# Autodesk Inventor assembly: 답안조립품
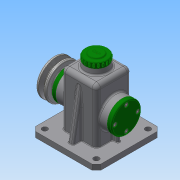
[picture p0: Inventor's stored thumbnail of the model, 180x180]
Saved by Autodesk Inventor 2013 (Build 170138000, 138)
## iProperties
Created: 2018-10
Part Number: 답안조립품
Document SubType Name: Assembly
Designer: Administrator
Author: Administrator
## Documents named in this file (14)
- C:\Users\Administrator\Desktop\481013V1014\답안조립품.iam
- C:\Users\Administrator\Desktop\481013V1014\본체.ipt
- C:\Users\Administrator\Desktop\481013V1014\V-벨트풀리.ipt
- C:\Users\Administrator\Desktop\481013V1014\뒤커버.ipt
- C:\Users\Administrator\Desktop\481013V1014\멈춤링 15 x 1.ipt
- C:\Users\Administrator\Desktop\481013V1014\베어링 15 x 35 x 11.ipt
- C:\Users\Administrator\Desktop\481013V1014\볼트 M4 x 10.ipt
- C:\Users\Administrator\Desktop\481013V1014\볼트 M6 x 12.ipt
- C:\Users\Administrator\Desktop\481013V1014\상부캡.ipt
- C:\Users\Administrator\Desktop\481013V1014\앞커버.ipt
- C:\Users\Administrator\Desktop\481013V1014\오일실 15 25 7.ipt
- C:\Users\Administrator\Desktop\481013V1014\와셔.ipt
- C:\Users\Administrator\Desktop\481013V1014\축.ipt
- C:\Users\Administrator\Desktop\481013V1014\키 5 x 5 x 14.ipt
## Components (1 placed, 1 different names)
1. V-벨트풀리:1
